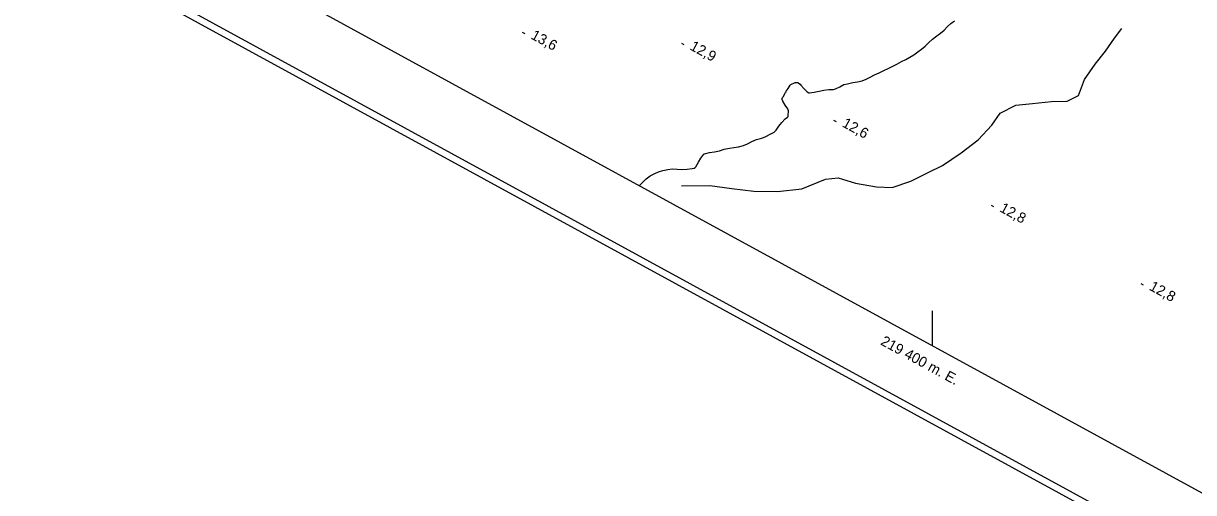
# Model space of a CAD drawing. Extents: x 219136 to 222520, y 5421589 to 5424530.
# Drawn here: x 219135.9 to 219475.9, y 5422818.4 to 5422954.8 of the extents above; entities that cross this region are included whole.
import ezdxf

# ---------------------------------------------------------------- set-up
doc = ezdxf.new("R2010")
doc.units = 0
for name, color, linetype in [('Level 22', 7, 'Continuous'), ('Level 3', 7, 'Continuous'), ('Level 4', 7, 'Continuous'), ('Level 60', 7, 'Continuous'), ('Level 61', 7, 'Continuous')]:
    doc.layers.add(name, color=color, linetype=linetype)

msp = doc.modelspace()

# ---------------------------------------------------------------- linework, layer by layer
at = {"layer": 'Level 22'}
msp.add_lwpolyline([(219327.15, 5422907.62), (219335.35, 5422907.63), (219341.77, 5422906.78), (219348.09, 5422906.06), (219355.02, 5422905.92), (219362.11, 5422906.74), (219368.93, 5422909.51), (219372.62, 5422909.91), (219377.67, 5422908.33), (219383.76, 5422907.27), (219388.31, 5422907.06), (219393.72, 5422908.9), (219398.73, 5422911.47), (219402.91, 5422913.5), (219408.37, 5422917.19), (219413.27, 5422920.96), (219417.3, 5422925.2), (219419.68, 5422928.72), (219424.21, 5422931.05), (219429.12, 5422931.51), (219434.65, 5422932.09), (219439.15, 5422932.18), (219442.41, 5422933.87), (219444.15, 5422938.46), (219447.3, 5422942.96), (219450.33, 5422946.76), (219452.91, 5422950.53), (219455.04, 5422953.32)], dxfattribs=at)
at = {"layer": 'Level 3'}
for p, q in [((219280.87, 5422952.21), (219281.58, 5422951.83)), ((219327.08, 5422949.04), (219327.78, 5422948.66)), ((219371.32, 5422926.67), (219372.02, 5422926.29)), ((219417.08, 5422902), (219417.78, 5422901.62)), ((219460.53, 5422879.22), (219461.23, 5422878.84))]:
    msp.add_line(p, q, dxfattribs=at)
at = {"layer": 'Level 4'}
for points in [[(219395.76, 5422946.5), (219396.87, 5422947.33), (219397.86, 5422948.14), (219398.91, 5422949.18), (219400.03, 5422950.19), (219401.28, 5422951.16), (219402.33, 5422951.95), (219403.39, 5422952.85), (219404.4, 5422953.88), (219405.37, 5422954.77), (219406.46, 5422955.51)], [(219357.79, 5422935.51), (219358.09, 5422935.9), (219358.69, 5422936.86), (219358.92, 5422936.98), (219360.14, 5422937.58), (219360.67, 5422937.65), (219360.92, 5422937.57), (219361.14, 5422937.43), (219361.6, 5422937.1), (219361.75, 5422936.88), (219362.63, 5422935.89), (219363.59, 5422934.88), (219364.09, 5422934.6), (219364.34, 5422934.59), (219365.67, 5422934.8), (219367.07, 5422935.06), (219368.5, 5422935.39), (219369.89, 5422935.59), (219371.27, 5422935.55), (219371.85, 5422935.74), (219373.1, 5422936.38), (219374.3, 5422937.01), (219375.35, 5422937.25), (219376.89, 5422937.65), (219378.23, 5422937.83), (219379.6, 5422938.09), (219380.77, 5422938.59), (219381.9, 5422939.18), (219383.14, 5422939.82), (219384.5, 5422940.41), (219385.9, 5422941.06), (219387.16, 5422941.71), (219388.31, 5422942.29), (219389.69, 5422942.98), (219391.06, 5422943.69), (219392.32, 5422944.34), (219393.48, 5422944.95), (219394.63, 5422945.63), (219395.76, 5422946.5)], [(219314.87, 5422907.71), (219315.85, 5422908.67), (219316.85, 5422909.65), (219318.06, 5422910.48), (219319.33, 5422911.13), (219320.47, 5422911.65), (219321.67, 5422912.05), (219323.17, 5422912.37), (219324.44, 5422912.49), (219325.81, 5422912.44), (219327.18, 5422912.3), (219328.72, 5422912.47), (219330.25, 5422912.59), (219330.81, 5422912.72), (219331.04, 5422912.88), (219331.25, 5422913.13), (219332.01, 5422914.42), (219332.76, 5422915.64), (219333.56, 5422916.75), (219333.83, 5422916.89), (219335.25, 5422917.26), (219336.71, 5422917.42), (219338.18, 5422917.76), (219339.49, 5422918.2), (219341.07, 5422918.54), (219342.31, 5422918.75), (219343.65, 5422918.96), (219345.11, 5422919.31), (219346.31, 5422919.83), (219347.58, 5422920.46), (219348.93, 5422921), (219350.42, 5422921.46), (219351.62, 5422921.96), (219352.83, 5422922.57), (219354, 5422923.18), (219354.63, 5422923.71), (219355.42, 5422924.92), (219356.27, 5422925.96), (219357.26, 5422927.02), (219357.91, 5422927.49), (219358.06, 5422927.73), (219358.14, 5422928.01), (219358.24, 5422929.34), (219358.14, 5422929.66), (219358.01, 5422929.92), (219357.21, 5422931.01), (219356.58, 5422932.18), (219356.39, 5422932.7), (219356.41, 5422932.95), (219356.5, 5422933.23), (219356.63, 5422933.45), (219357.34, 5422934.67), (219357.52, 5422934.87), (219357.55, 5422935.16), (219357.79, 5422935.51)]]:
    msp.add_lwpolyline(points, dxfattribs=at)
at = {"layer": 'Level 60'}
for points in [[(219135.93, 5422982.66), (219981.09, 5424529.89), (222519.95, 5423143.06), (221674.79, 5421595.83), (219135.93, 5422982.66)], [(219138.65, 5422983.46), (219981.9, 5424527.19), (222517.24, 5423142.28), (221673.99, 5421598.55), (219138.65, 5422983.46)]]:
    msp.add_lwpolyline(points, dxfattribs=at)
msp.add_lwpolyline([(219164.83, 5422989.67), (219989.85, 5424500.03), (222033.74, 5423383.57), (221208.72, 5421873.21)], close=True, dxfattribs=at)
at = {"layer": 'Level 61'}
msp.add_line((219400, 5422861.21), (219400, 5422871.21), dxfattribs=at)

# ---------------------------------------------------------------- texts
at = {"layer": 'Level 3'}
for s, p in [('13,6', (219283.12, 5422950.48)), ('12,9', (219329.32, 5422947.3)), ('12,6', (219373.56, 5422924.93)), ('12,8', (219419.32, 5422900.26)), ('12,8', (219462.77, 5422877.48))]:
    msp.add_text(s, height=3, rotation=331.383, dxfattribs=at).set_placement(p)
at = {"layer": 'Level 61'}
msp.add_text('219 400 m. E.', height=3, rotation=331.3547, dxfattribs=at).set_placement((219384.73, 5422861.56))

doc.saveas('drawing.dxf')
